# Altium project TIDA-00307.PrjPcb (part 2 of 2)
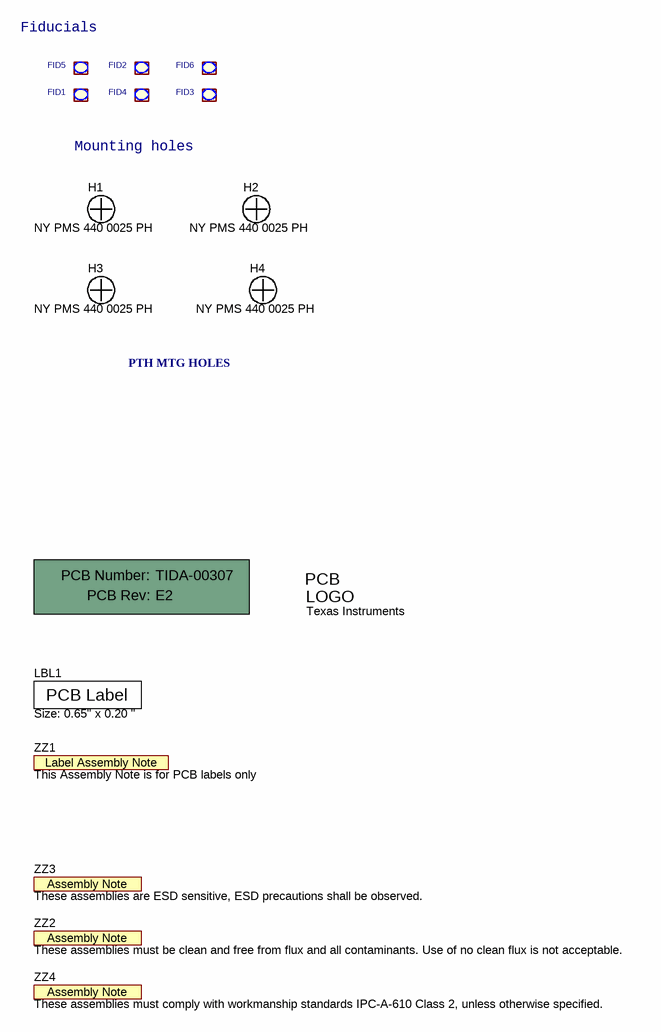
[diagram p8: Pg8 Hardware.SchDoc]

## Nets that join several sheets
+3.3V: Pg3  ADC1,ADC2 (7 pins), Pg7 Power Supply (6 pins)
+5V: Pg3  ADC1,ADC2 (10 pins), Pg7 Power Supply (6 pins)
+DC_IN: Pg3  ADC1,ADC2 (D15.1), Pg7 Power Supply (9 pins)
SGND: Pg3  ADC1,ADC2 (45 pins), Pg4 ADC1,ADC2 INPUTS (17 pins), Pg5 ADC1 FILTERS (18 pins), Pg6 ADC2 FILTERS (17 pins), Pg7 Power Supply (20 pins)
SGND1: Pg4 ADC1,ADC2 INPUTS (C1.1 C2.1 D7.1), Pg5 ADC1 FILTERS (17 pins), Pg6 ADC2 FILTERS (16 pins)
2AIN0: Pg3  ADC1,ADC2 (R65.1), Pg6 ADC2 FILTERS (R78.2)
2AIN1: Pg3  ADC1,ADC2 (R75.1), Pg6 ADC2 FILTERS (R83.2)
2AIN2: Pg3  ADC1,ADC2 (R84.2), Pg6 ADC2 FILTERS (R97.2)
2AIN3: Pg3  ADC1,ADC2 (R86.2), Pg6 ADC2 FILTERS (R98.2)
2AIN4: Pg3  ADC1,ADC2 (R88.2), Pg6 ADC2 FILTERS (R99.2)
2AIN5: Pg3  ADC1,ADC2 (R90.2), Pg6 ADC2 FILTERS (R100.2)
2AIN6: Pg3  ADC1,ADC2 (R62.1), Pg6 ADC2 FILTERS (R61.2)
2AIN7: Pg3  ADC1,ADC2 (R64.1), Pg6 ADC2 FILTERS (R73.2)
2IN_AIN0: Pg4 ADC1,ADC2 INPUTS (J13.1), Pg6 ADC2 FILTERS (R80.1)
2IN_AIN0_N: Pg3  ADC1,ADC2 (R70.1), Pg4 ADC1,ADC2 INPUTS (J13.2 R146.2)
2IN_AIN1: Pg4 ADC1,ADC2 INPUTS (J14.1), Pg6 ADC2 FILTERS (R94.1)
2IN_AIN1_N: Pg3  ADC1,ADC2 (R74.1), Pg4 ADC1,ADC2 INPUTS (J14.2 R147.2)
2IN_AIN2: Pg4 ADC1,ADC2 INPUTS (J15.1), Pg6 ADC2 FILTERS (R111.1)
2IN_AIN2_N: Pg3  ADC1,ADC2 (R85.2), Pg4 ADC1,ADC2 INPUTS (J15.2 R148.2)
2IN_AIN3: Pg4 ADC1,ADC2 INPUTS (J16.1), Pg6 ADC2 FILTERS (R112.1)
2IN_AIN3_N: Pg3  ADC1,ADC2 (R87.2), Pg4 ADC1,ADC2 INPUTS (J16.2 R149.2)
2IN_AIN4: Pg4 ADC1,ADC2 INPUTS (J17.1), Pg6 ADC2 FILTERS (R113.1)
2IN_AIN4_N: Pg3  ADC1,ADC2 (R89.2), Pg4 ADC1,ADC2 INPUTS (J17.2 R150.2)
2IN_AIN5: Pg4 ADC1,ADC2 INPUTS (J18.1), Pg6 ADC2 FILTERS (R114.1)
2IN_AIN5_N: Pg3  ADC1,ADC2 (R91.2), Pg4 ADC1,ADC2 INPUTS (J18.2 R151.2)
2IN_AIN6: Pg4 ADC1,ADC2 INPUTS (J10.1), Pg6 ADC2 FILTERS (R57.1)
2IN_AIN6_N: Pg3  ADC1,ADC2 (R63.1), Pg4 ADC1,ADC2 INPUTS (J10.2 R132.2)
2IN_AIN7: Pg4 ADC1,ADC2 INPUTS (J12.1), Pg6 ADC2 FILTERS (R69.1)
2IN_AIN7_N: Pg3  ADC1,ADC2 (R66.1), Pg4 ADC1,ADC2 INPUTS (J12.2 R141.2)
AIN0: Pg3  ADC1,ADC2 (R25.1), Pg5 ADC1 FILTERS (R12.2)
AIN1: Pg3  ADC1,ADC2 (R22.1), Pg5 ADC1 FILTERS (R10.2)
AIN2: Pg3  ADC1,ADC2 (R39.2), Pg5 ADC1 FILTERS (R18.2)
AIN3: Pg3  ADC1,ADC2 (R43.2), Pg5 ADC1 FILTERS (R31.2)
AIN4: Pg3  ADC1,ADC2 (R51.2), Pg5 ADC1 FILTERS (R38.2)
AIN5: Pg3  ADC1,ADC2 (R54.2), Pg5 ADC1 FILTERS (R49.2)
AIN6: Pg3  ADC1,ADC2 (R28.1), Pg5 ADC1 FILTERS (R16.2)
AIN7: Pg3  ADC1,ADC2 (R27.1), Pg5 ADC1 FILTERS (R14.2)
IN_AIN0: Pg4 ADC1,ADC2 INPUTS (J2.1), Pg5 ADC1 FILTERS (R2.1)
IN_AIN0_N: Pg3  ADC1,ADC2 (R23.1), Pg4 ADC1,ADC2 INPUTS (J2.2 R119.2)
IN_AIN1: Pg4 ADC1,ADC2 INPUTS (J1.1), Pg5 ADC1 FILTERS (R1.1)
IN_AIN1_N: Pg3  ADC1,ADC2 (R21.1), Pg4 ADC1,ADC2 INPUTS (J1.2 R118.2)
IN_AIN2: Pg4 ADC1,ADC2 INPUTS (J5.1), Pg5 ADC1 FILTERS (R19.1)
IN_AIN2_N: Pg3  ADC1,ADC2 (R33.2), Pg4 ADC1,ADC2 INPUTS (J5.2 R120.2)
IN_AIN3: Pg4 ADC1,ADC2 INPUTS (J6.1), Pg5 ADC1 FILTERS (R29.1)
IN_AIN3_N: Pg3  ADC1,ADC2 (R44.2), Pg4 ADC1,ADC2 INPUTS (J6.2 R121.2)
IN_AIN4: Pg4 ADC1,ADC2 INPUTS (J8.1), Pg5 ADC1 FILTERS (R36.1)
IN_AIN4_N: Pg3  ADC1,ADC2 (R46.2), Pg4 ADC1,ADC2 INPUTS (J8.2 R129.2)
IN_AIN5: Pg4 ADC1,ADC2 INPUTS (J9.1), Pg5 ADC1 FILTERS (R48.1)
IN_AIN5_N: Pg3  ADC1,ADC2 (R50.2), Pg4 ADC1,ADC2 INPUTS (J9.2 R130.2)
IN_AIN6: Pg4 ADC1,ADC2 INPUTS (J4.1), Pg5 ADC1 FILTERS (R4.1)
IN_AIN6_N: Pg3  ADC1,ADC2 (R26.1), Pg4 ADC1,ADC2 INPUTS (J4.2 R117.2)
IN_AIN7: Pg4 ADC1,ADC2 INPUTS (J3.1), Pg5 ADC1 FILTERS (R3.1)
IN_AIN7_N: Pg3  ADC1,ADC2 (R24.1), Pg4 ADC1,ADC2 INPUTS (J3.2 R116.2)

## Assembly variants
001: not fitted C9 C34 D9 D20 Q1 Q2 R5 R6 R7 R8 R9 R11 R13 R15 R17 R20 R30 R32 R37 R40 R41 R42 R47 R52 R53 R59 R60 R68 R71 R72 R76 R77 R79 R81 R82 R95 R96 R101 R102 R103 R104 R105 R106 R107 R108 R109 R110 R123 R128 R133 R135 R144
